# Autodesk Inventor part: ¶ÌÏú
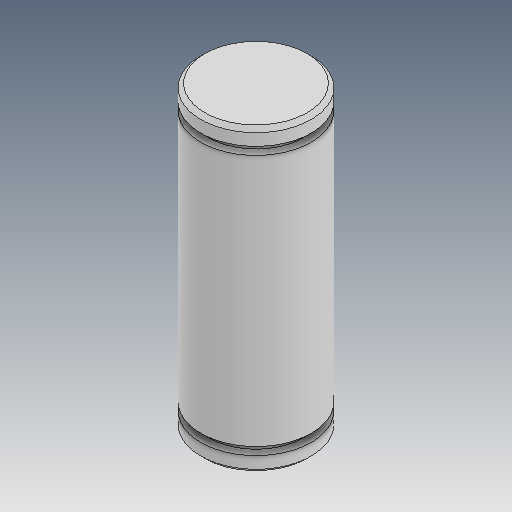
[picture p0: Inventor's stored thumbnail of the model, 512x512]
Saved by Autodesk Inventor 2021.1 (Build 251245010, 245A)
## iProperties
Created: 2019-04
Part Number: ¶ÌÏú
Material: Ogólny
Document SubType Name: Modeling
Designer: user
Density: 1 g/cm^3
Appearance: Domyślna
Author: user
Revision Number: ÈÎºÎ
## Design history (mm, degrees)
feature "ÊäÈë1"
node "Bryła1"
